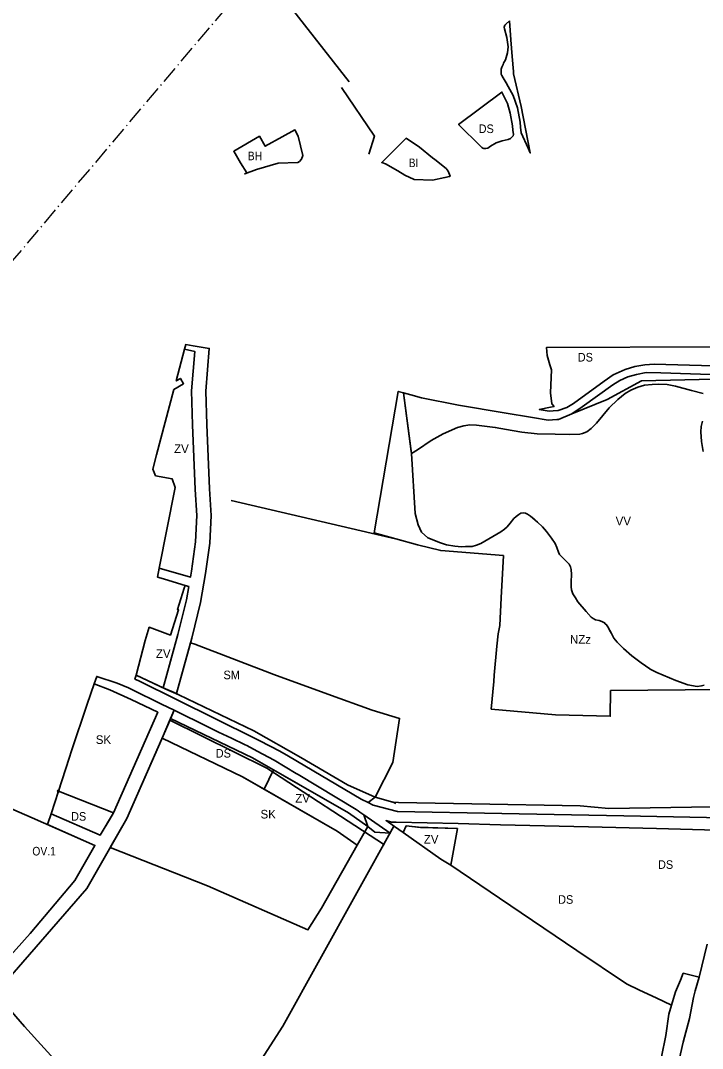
# Model space of a CAD drawing. Extents: x -650276 to -642489, y -1074311 to -1066658.
# Drawn here: x -646170 to -645218, y -1071706 to -1070271 of the extents above; entities that cross this region are included whole.
import ezdxf

# ---------------------------------------------------------------- set-up
doc = ezdxf.new("R2010")
doc.units = 0
doc.header["$LTSCALE"] = 4.8
doc.header["$PDMODE"] = 32
doc.header["$PDSIZE"] = 2.4
doc.linetypes.add('DOT_DASHED', pattern=[7.7, 5, -1.2, 0.3, -1.2])
for name, color, linetype, lineweight in [('1', 7, 'Continuous', 35), ('11', 7, 'Continuous', 35), ('15', 7, 'Continuous', 35), ('18', 7, 'Continuous', 35), ('2', 7, 'Continuous', 35), ('20', 7, 'Continuous', 35), ('24', 7, 'Continuous', 35), ('40', 7, 'Continuous', 35), ('45', 7, 'Continuous', 35), ('46', 7, 'Continuous', 35), ('54', 7, 'Continuous', 35), ('55', 7, 'Continuous', 53)]:
    doc.layers.add(name, color=color, linetype=linetype, lineweight=lineweight)
doc.layers.add('62', color=7, linetype='Continuous')

msp = doc.modelspace()

# ---------------------------------------------------------------- linework, layer by layer
at = {"layer": '1'}
msp.add_lwpolyline([(-645862.66, -1070469.5), (-645853.98, -1070483.81), (-645856.87, -1070485.24), (-645840.59, -1070479), (-645810.44, -1070470.17), (-645782.57, -1070469.22), (-645780.38, -1070467.64), (-645777.8, -1070464.4), (-645776.04, -1070459.38), (-645782.13, -1070432.59), (-645786.9, -1070423.81), (-645804.58, -1070433.53), (-645828.24, -1070446.54), (-645836.32, -1070432.55), (-645872.35, -1070453.55)], close=True, dxfattribs=at)
at = {"layer": '11'}
msp.add_lwpolyline([(-646066.165, -1071422.155), (-646153.5, -1071383.85), (-646208.577, -1071360.044), (-646241.68, -1071416.887), (-646258.487, -1071439.265), (-646275.615, -1071460.886), (-646289.976, -1071477.514), (-646330.914, -1071521.11), (-646324, -1071535), (-646217.978, -1071613.552), (-646211.407, -1071606.247), (-646156.471, -1071545.166), (-646094.063, -1071471.007)], close=True, dxfattribs=at)
at = {"layer": '15'}
for points in [[(-645487.361, -1070271.37), (-645491.94, -1070275.85), (-645491.94, -1070275.85), (-645493.8, -1070277.67), (-645494.57, -1070280.34), (-645494.12, -1070282.52), (-645490.79, -1070294.93), (-645489.31, -1070307.77), (-645490.03, -1070316.27), (-645493.05, -1070326.11), (-645495.44, -1070330.67), (-645496.12, -1070332.34), (-645497.83, -1070336.16), (-645498.75, -1070338.98), (-645499.01, -1070340.96), (-645499.09, -1070343.91), (-645498.74, -1070345.87), (-645498, -1070347.74), (-645496.02, -1070351.15), (-645491.97, -1070358.14), (-645488.99, -1070362.96)], [(-645487.361, -1070271.37), (-645491.94, -1070275.85), (-645491.94, -1070275.85), (-645493.8, -1070277.67), (-645494.57, -1070280.34), (-645494.12, -1070282.52), (-645490.79, -1070294.93), (-645489.31, -1070307.77), (-645490.03, -1070316.27), (-645493.05, -1070326.11), (-645495.44, -1070330.67), (-645496.12, -1070332.34), (-645497.83, -1070336.16), (-645498.75, -1070338.98), (-645499.01, -1070340.96), (-645499.09, -1070343.91), (-645498.74, -1070345.87), (-645498, -1070347.74), (-645496.02, -1070351.15), (-645491.97, -1070358.14)], [(-645458.32, -1070455.91), (-645471, -1070391), (-645481.67, -1070345.39), (-645481.65, -1070342.07), (-645483.34, -1070321.17), (-645484.27, -1070309.7), (-645485.21, -1070298.03), (-645487.361, -1070271.37)], [(-645483.34, -1070321.17), (-645484.27, -1070309.7), (-645485.21, -1070298.03), (-645487.361, -1070271.37)], [(-645482.16, -1070375.96), (-645476.12, -1070393.13), (-645472.61, -1070413.13), (-645471.87, -1070419.96), (-645470.99, -1070428.07), (-645461.32, -1070449.31), (-645458.32, -1070455.91), (-645471, -1070391), (-645481.67, -1070345.39), (-645481.65, -1070342.07), (-645483.34, -1070321.17)], [(-645491.97, -1070358.14), (-645488.99, -1070362.96), (-645482.16, -1070375.96)], [(-645488.99, -1070362.96), (-645482.16, -1070375.96), (-645476.12, -1070393.13), (-645472.61, -1070413.13), (-645471.87, -1070419.96), (-645470.99, -1070428.07), (-645461.32, -1070449.31), (-645458.32, -1070455.91)], [(-646197.398, -1071620.579), (-646077.593, -1071482.499), (-646021.674, -1071384.575), (-645964.396, -1071254.314), (-645955.342, -1071233.725), (-645973.324, -1071224.925), (-645989.7, -1071216.91), (-645997.62, -1071213.03), (-646019.41, -1071202.36), (-646035.06, -1071195.87), (-646063.59, -1071186.33), (-646067.097, -1071196.699), (-646045.462, -1071204.917), (-646015.387, -1071218.854), (-645978.403, -1071236.481), (-646040.084, -1071376.813), (-646058.719, -1071407.796), (-646127.301, -1071378.036), (-646131.79, -1071391.83), (-646132.229, -1071393.179), (-646066.165, -1071422.155), (-646094.063, -1071471.007), (-646156.471, -1071545.166), (-646211.407, -1071606.247)], [(-645701.44, -1071372.25), (-645782.32, -1071323.5), (-645784.92, -1071321.93), (-645815.65, -1071303.41), (-645839.37, -1071290.6), (-645854.1, -1071282.93), (-645856.26, -1071281.91), (-645875.48, -1071272.81), (-645893.41, -1071264.04), (-645907.62, -1071257.08), (-645955.342, -1071233.725), (-645960.34, -1071245.09), (-645846, -1071300), (-645712, -1071377), (-645712, -1071377)], [(-645712, -1071377), (-645685.098, -1071395.824), (-645690.677, -1071379.721)]]:
    msp.add_lwpolyline(points, dxfattribs=at)
for points in [[(-645911.345, -1070788.463), (-645906.373, -1070728.716), (-645929.077, -1070725.068), (-645939.27, -1070723.43), (-645940.955, -1070729.799), (-645926.784, -1070732.812), (-645931.369, -1070787.913), (-645930.036, -1070835.367), (-645926.084, -1070925.481), (-645923.919, -1070961.855), (-645925.626, -1070998.754), (-645931.24, -1071039.686), (-645932.635, -1071047.688), (-645976.17, -1071035.39), (-645978.58, -1071047.68), (-645973.77, -1071049.17), (-645968.97, -1071050.66), (-645940.25, -1071059.59), (-645934.978, -1071061.119), (-645938.15, -1071079.311), (-645950.283, -1071128.057), (-645970.966, -1071202.169), (-645952.419, -1071210.117), (-645930.943, -1071133.161), (-645918.57, -1071083.449), (-645911.474, -1071042.764), (-645905.69, -1071000.578), (-645903.891, -1070961.723), (-645906.11, -1070924.449), (-645910.048, -1070834.649)], [(-645694.15, -1071357.83), (-645684.785, -1071362.539), (-645674.947, -1071355.071), (-645713.428, -1071337.765), (-645778.69, -1071299.362), (-645844.079, -1071262.487), (-645948.761, -1071211.885), (-645967, -1071204), (-646008.714, -1071184.746), (-646010.14, -1071190.08), (-646004.65, -1071192.55), (-645951.118, -1071219.11), (-645843.45, -1071272.53), (-645835.76, -1071276.35), (-645808.13, -1071290.78), (-645795.97, -1071297.93), (-645694.15, -1071357.83)]]:
    msp.add_lwpolyline(points, close=True, dxfattribs=at)
msp.add_arc((-645538.107, -1071148.434), 277.076, 233.87926, 236.5888, dxfattribs=at)
at = {"layer": '18'}
for points in [[(-645926.81, -1071141.595), (-645932.502, -1071139.426), (-645952.419, -1071210.117), (-645948.761, -1071211.885)], [(-645678.86, -1071233.58), (-645741.09, -1071211.36), (-645816.47, -1071183.63), (-645926.81, -1071141.595)], [(-645948.761, -1071211.885), (-645844.079, -1071262.487), (-645778.69, -1071299.362), (-645713.428, -1071337.765), (-645674.947, -1071355.071)], [(-645674.947, -1071355.071), (-645650.09, -1071306.433), (-645640.737, -1071244.963), (-645678.86, -1071233.58)]]:
    msp.add_lwpolyline(points, dxfattribs=at)
at = {"layer": '2'}
msp.add_lwpolyline([(-645594.769, -1070494.065), (-645577.47, -1070490.3), (-645571.13, -1070488.89), (-645569.97, -1070488.3), (-645572.86, -1070481.41), (-645575.7, -1070477.77), (-645591.49, -1070465.19), (-645594.62, -1070462.7), (-645612.77, -1070447.82), (-645631.63, -1070435.3), (-645636.42, -1070439.93), (-645648.9, -1070452.38), (-645665.6, -1070469.04), (-645660.29, -1070471.12), (-645643.4, -1070481.02), (-645633.35, -1070486.91), (-645620.22, -1070493)], close=True, dxfattribs=at)
at = {"layer": '20'}
for points in [[(-645990.48, -1071263.958), (-645978.403, -1071236.481), (-646015.387, -1071218.854), (-646045.462, -1071204.917), (-646067.097, -1071196.699), (-646076.713, -1071225.138)], [(-646076.713, -1071225.138), (-646098.66, -1071290.03), (-646102.011, -1071300.326), (-646117.031, -1071346.48)], [(-646117.031, -1071346.48), (-646040.084, -1071376.813), (-645990.48, -1071263.958)]]:
    msp.add_lwpolyline(points, dxfattribs=at)
msp.add_lwpolyline([(-645699.825, -1071422.134), (-645728.105, -1071402.346), (-645859.986, -1071326.563), (-645972.422, -1071272.568), (-646021.674, -1071384.575), (-646044.948, -1071425.333), (-645909.13, -1071478.56), (-645768.62, -1071540.17), (-645749.631, -1071509.908)], close=True, dxfattribs=at)
msp.add_point((-646117.031, -1071346.48), dxfattribs=at)
at = {"layer": '24'}
for points in [[(-645497.81, -1070370.93), (-645497.81, -1070370.93), (-645490.19, -1070386.97), (-645486.54, -1070400.38), (-645483.29, -1070417.99), (-645482.62, -1070423.93), (-645481.93, -1070430.04), (-645482.18, -1070432.13), (-645485.67, -1070435.7), (-645489.34, -1070437.05), (-645497.33, -1070438.82), (-645505.88, -1070441.74), (-645513.81, -1070446.24), (-645517.44, -1070449.23), (-645517.95, -1070449.45), (-645520.4, -1070449.87), (-645521.41, -1070449.84), (-645522.95, -1070449.61), (-645524.42, -1070449.16), (-645525.75, -1070448.41), (-645527.34, -1070447.1), (-645558.36, -1070416.1)], [(-645202.41, -1070726.571), (-645197.539, -1070753.128), (-645202.96, -1070752.89), (-645285.11, -1070750.69), (-645298.41, -1070751.48), (-645312.2, -1070753.77), (-645325.82, -1070757.94), (-645342.41, -1070765.76), (-645354.98, -1070774.28), (-645398.04, -1070805.44), (-645407.37, -1070810.95), (-645419.18, -1070815.44), (-645426.36, -1070815.78), (-645432.07, -1070816.05), (-645445.81, -1070814.06), (-645429.993, -1070810.647), (-645424.969, -1070809.563), (-645428.39, -1070806.09), (-645430, -1070790.68), (-645428.73, -1070758.67), (-645430.84, -1070751.43), (-645434.53, -1070738.77), (-645435.711, -1070727.497)], [(-645829.706, -1071343.963), (-645816.714, -1071316.828), (-645846, -1071300), (-645960.34, -1071245.09), (-645972.422, -1071272.568), (-645859.986, -1071326.563)], [(-646045.393, -1071385.64), (-646040.084, -1071376.813), (-646117.031, -1071346.48), (-646127.301, -1071378.036), (-646058.719, -1071407.796)], [(-645675.177, -1071403.922), (-645675.177, -1071403.922), (-645653.742, -1071405.36), (-645690.677, -1071379.721), (-645685.098, -1071395.824)]]:
    msp.add_lwpolyline(points, close=True, dxfattribs=at)
for points in [[(-645179.18, -1070765.86), (-645275.8, -1070762.66), (-645296.51, -1070762.52), (-645309.78, -1070764.88), (-645321.9, -1070768.47), (-645333.12, -1070773.33), (-645342.94, -1070779.31), (-645385.99, -1070810.35), (-645400.05, -1070819.84), (-645351, -1070800), (-645303, -1070774), (-645182, -1070771)], [(-645204.341, -1071368.19), (-645348.55, -1071370.559), (-645388.619, -1071366.991), (-645539.738, -1071364.092), (-645642.431, -1071362.259), (-645650.28, -1071362.07), (-645674.947, -1071355.071), (-645684.785, -1071362.539), (-645677.58, -1071366.16), (-645643.56, -1071374.75), (-645497.84, -1071377.53), (-645327.76, -1071380.76), (-645166.34, -1071384.07)], [(-645164.76, -1071401.79), (-645281.92, -1071398.82), (-645376.87, -1071396.41), (-645499.65, -1071393.3), (-645558.9, -1071391.8), (-645645.368, -1071389.96), (-645651.93, -1071389.82), (-645659.6, -1071387.71), (-645647.727, -1071396.036), (-645635.795, -1071404.403), (-645631.44, -1071394.9), (-645614.201, -1071396.844), (-645560.11, -1071398.7), (-645569.07, -1071449.88), (-645501.37, -1071495.68), (-645393.34, -1071568.75), (-645324.17, -1071615.53), (-645324.17, -1071615.53), (-645305.78, -1071624.13), (-645282.54, -1071634.997), (-645261.094, -1071645.025), (-645255.662, -1071626.67), (-645248.786, -1071610.383), (-645244.81, -1071600.61), (-645222.48, -1071606.08), (-645222.48, -1071606.08), (-645211.27, -1071560.01)], [(-645222.48, -1071606.08), (-645244.81, -1071600.61), (-645248.786, -1071610.383), (-645255.662, -1071626.67)], [(-645222.48, -1071606.08), (-645244.81, -1071600.61), (-645248.786, -1071610.383), (-645255.662, -1071626.67)], [(-645339.904, -1072462.677), (-645347.551, -1072443.527), (-645347.677, -1072391.355), (-645346.62, -1072330.914), (-645343.458, -1072278.998), (-645339.908, -1072235.158), (-645335.367, -1072185.207), (-645325.498, -1072102.789), (-645309.01, -1071998.147), (-645285.617, -1071875.733), (-645244.798, -1071696.585), (-645235.793, -1071663.703), (-645230.436, -1071634.261), (-645227.905, -1071625.277), (-645222.48, -1071606.08)], [(-645339.904, -1072462.677), (-645347.551, -1072443.527), (-645347.677, -1072391.355), (-645346.62, -1072330.914), (-645343.458, -1072278.998), (-645339.908, -1072235.158), (-645335.367, -1072185.207), (-645325.498, -1072102.789), (-645309.01, -1071998.147), (-645285.617, -1071875.733), (-645244.798, -1071696.585), (-645235.793, -1071663.703), (-645230.436, -1071634.261), (-645227.905, -1071625.277), (-645222.48, -1071606.08)], [(-645255.662, -1071626.67), (-645261.094, -1071645.025), (-645264.841, -1071657.687), (-645269.077, -1071687.396), (-645274.868, -1071717.176), (-645286.175, -1071761.228), (-645300.076, -1071820.179), (-645313.153, -1071883.081), (-645326.343, -1071952.807)], [(-645255.662, -1071626.67), (-645261.094, -1071645.025), (-645264.841, -1071657.687), (-645269.077, -1071687.396), (-645274.868, -1071717.176), (-645286.175, -1071761.228), (-645300.076, -1071820.179), (-645313.153, -1071883.081)]]:
    msp.add_lwpolyline(points, dxfattribs=at)
at = {"layer": '40'}
for points in [[(-645932.635, -1071047.688), (-645931.24, -1071039.686), (-645925.626, -1070998.754), (-645923.919, -1070961.855), (-645926.084, -1070925.481), (-645930.036, -1070835.367), (-645931.369, -1070787.913), (-645926.784, -1070732.812), (-645940.955, -1070729.799), (-645952.65, -1070773.98), (-645946.81, -1070770.47), (-645942.3, -1070777.96), (-645955.86, -1070786.21), (-645980.01, -1070877.28), (-645985.28, -1070897.13), (-645981.48, -1070906.35), (-645958.21, -1070910.84), (-645954.01, -1070922.8), (-645954.492, -1070925.251), (-645976.17, -1071035.39)], [(-645970.966, -1071202.169), (-645950.283, -1071128.057), (-645938.15, -1071079.311), (-645934.978, -1071061.119), (-645940.25, -1071059.59), (-645941.45, -1071063.3), (-645950.96, -1071092.8), (-645949.21, -1071093.62), (-645960.66, -1071128.71), (-645990.14, -1071117.76), (-645995.74, -1071136.22), (-646008.714, -1071184.746)], [(-645712, -1071377), (-645816.714, -1071316.828), (-645829.706, -1071343.963), (-645728.105, -1071402.346), (-645699.825, -1071422.134), (-645685.098, -1071395.824)], [(-645583.18, -1071441.3), (-645580.947, -1071442.658), (-645569.07, -1071449.88), (-645560.11, -1071398.7), (-645611.58, -1071397.14), (-645631.44, -1071394.9), (-645635.795, -1071404.403)]]:
    msp.add_lwpolyline(points, close=True, dxfattribs=at)
at = {"layer": '45'}
for points in [[(-645217.086, -1070791.58), (-645233.003, -1070787.399), (-645255.407, -1070781.443), (-645267.315, -1070779.162), (-645279.349, -1070778.402), (-645288.343, -1070778.909), (-645298.731, -1070780.176), (-645307.923, -1070782.557), (-645317.677, -1070786.866), (-645325.785, -1070791.428), (-645336.046, -1070799.793), (-645348.318, -1070811.675), (-645366.02, -1070832.94), (-645373.241, -1070840.417), (-645379.448, -1070845.106), (-645385.148, -1070847.387), (-645389.329, -1070848.148), (-645404.15, -1070848.781), (-645423.364, -1070848.402), (-645448.7, -1070847.895), (-645470.235, -1070845.487), (-645483.61, -1070843.208), (-645507.299, -1070838.899), (-645533.268, -1070835.731), (-645542.642, -1070835.35), (-645550.832, -1070836.602), (-645560.079, -1070839.137), (-645579.841, -1070848.008), (-645596.689, -1070857.387), (-645615.817, -1070870.187), (-645624.321, -1070875.224), (-645618.798, -1070958.861), (-645615, -1070975), (-645610, -1070985), (-645601.41, -1070992.83), (-645583.707, -1071000.16), (-645575.406, -1071002.782), (-645563.698, -1071004.618), (-645554.524, -1071005.405), (-645548.534, -1071005.316), (-645539.622, -1071004.966), (-645533.156, -1071003.131), (-645527.302, -1071001.033), (-645521.535, -1070997.886), (-645499.204, -1070984.54), (-645494.223, -1070980.781), (-645490.641, -1070977.722), (-645486.534, -1070972.652), (-645481.466, -1070966.271), (-645477.971, -1070963.036), (-645474.301, -1070960.414), (-645471.418, -1070958.578), (-645468.185, -1070957.966), (-645464.865, -1070958.491), (-645462.069, -1070959.89), (-645457.875, -1070962.949), (-645452.982, -1070967.057), (-645448.001, -1070971.341), (-645441.361, -1070977.635), (-645435.443, -1070984.082), (-645428.541, -1070993.348), (-645423.648, -1071000.865), (-645421.21, -1071006.61), (-645419.026, -1071013.254), (-645417.453, -1071016.051), (-645412.735, -1071020.771), (-645407.492, -1071025.841), (-645404.172, -1071029.687), (-645402.194, -1071033.492), (-645401.408, -1071037.251), (-645400.796, -1071044.157), (-645401.233, -1071054.647), (-645401.408, -1071061.465), (-645400.796, -1071065.748), (-645398.979, -1071070.938), (-645395.234, -1071076.602), (-645395.222, -1071076.62), (-645391.902, -1071082.302), (-645380.193, -1071095.851), (-645373.291, -1071103.543), (-645370.698, -1071105.6), (-645367.028, -1071107.348), (-645362.223, -1071108.484), (-645358.326, -1071109.586), (-645358.203, -1071109.621), (-645354.883, -1071111.631)], [(-645216.991, -1070872.38), (-645219.351, -1070858.481), (-645220.312, -1070845.02), (-645219.787, -1070837.502), (-645217.778, -1070830.159)], [(-645354.883, -1071111.631), (-645353.555, -1071112.92), (-645352, -1071114.429), (-645349.99, -1071117.401), (-645347.631, -1071121.771), (-645345.097, -1071126.754), (-645341.689, -1071132.873), (-645336.884, -1071138.467), (-645328.059, -1071147.471), (-645316.308, -1071157.576), (-645303.551, -1071167.541), (-645291.581, -1071175.845), (-645290.83, -1071176.217), (-645281.707, -1071180.74), (-645254.845, -1071191.919), (-645238.506, -1071198.212), (-645225.487, -1071200.398), (-645225.487, -1071200.398), (-645219.283, -1071199.786), (-645215.351, -1071198.562)]]:
    msp.add_lwpolyline(points, dxfattribs=at)
at = {"layer": '46'}
for points in [[(-645182, -1070771), (-645303, -1070774), (-645351, -1070800), (-645400.05, -1070819.84), (-645418.67, -1070827.72), (-645421.09, -1070827.89), (-645433.49, -1070828.76), (-645455.184, -1070825.042), (-645494.82, -1070818.45), (-645558.3, -1070808), (-645610.25, -1070797.55), (-645625, -1070793.5), (-645635.482, -1070790.628), (-645624.513, -1070872.314), (-645624.321, -1070875.224), (-645615.817, -1070870.187), (-645596.689, -1070857.387), (-645579.841, -1070848.008), (-645560.079, -1070839.137), (-645550.832, -1070836.602), (-645542.642, -1070835.35), (-645533.268, -1070835.731), (-645507.299, -1070838.899), (-645483.61, -1070843.208), (-645470.235, -1070845.487), (-645448.7, -1070847.895), (-645423.364, -1070848.402), (-645404.15, -1070848.781), (-645389.329, -1070848.148), (-645385.148, -1070847.387), (-645379.448, -1070845.106), (-645373.241, -1070840.417), (-645366.02, -1070832.94), (-645348.318, -1070811.675), (-645336.046, -1070799.793), (-645325.785, -1070791.428), (-645317.677, -1070786.866), (-645307.923, -1070782.557), (-645298.731, -1070780.176), (-645288.343, -1070778.909), (-645279.349, -1070778.402), (-645267.315, -1070779.162), (-645255.407, -1070781.443), (-645233.003, -1070787.399), (-645217.086, -1070791.58)], [(-645346.31, -1071206.07), (-645189.902, -1071204.885), (-645130.749, -1070959.561), (-645098.438, -1070825.558), (-645100.268, -1070771.946), (-645143, -1070770), (-645161, -1070770)], [(-645225.487, -1071200.398), (-645238.506, -1071198.212), (-645254.845, -1071191.919), (-645281.707, -1071180.74), (-645290.83, -1071176.217), (-645291.581, -1071175.845), (-645303.551, -1071167.541), (-645316.308, -1071157.576), (-645328.059, -1071147.471), (-645336.884, -1071138.467), (-645341.689, -1071132.873), (-645345.097, -1071126.754), (-645349.99, -1071117.401), (-645352, -1071114.429), (-645354.883, -1071111.631), (-645358.203, -1071109.621), (-645362.223, -1071108.484), (-645367.028, -1071107.348), (-645370.698, -1071105.6), (-645373.291, -1071103.543), (-645380.193, -1071095.851), (-645391.902, -1071082.302), (-645395.222, -1071076.62), (-645398.979, -1071070.938), (-645400.796, -1071065.748), (-645401.408, -1071061.465), (-645401.233, -1071054.647), (-645400.796, -1071044.157), (-645401.408, -1071037.251), (-645402.194, -1071033.492), (-645404.172, -1071029.687), (-645407.492, -1071025.841), (-645412.735, -1071020.771), (-645417.453, -1071016.051), (-645419.026, -1071013.254), (-645421.21, -1071006.61), (-645423.648, -1071000.865), (-645428.541, -1070993.348), (-645435.443, -1070984.082), (-645441.361, -1070977.635), (-645448.001, -1070971.341), (-645457.875, -1070962.949), (-645462.069, -1070959.89), (-645464.865, -1070958.491), (-645468.185, -1070957.966), (-645471.418, -1070958.578), (-645474.301, -1070960.414), (-645477.971, -1070963.036), (-645481.466, -1070966.271), (-645486.534, -1070972.652), (-645490.641, -1070977.722), (-645494.223, -1070980.781), (-645499.204, -1070984.54), (-645521.535, -1070997.886), (-645527.302, -1071001.033), (-645533.156, -1071003.131), (-645539.622, -1071004.966), (-645548.534, -1071005.316), (-645554.524, -1071005.405), (-645563.698, -1071004.618), (-645575.406, -1071002.782), (-645583.707, -1071000.16), (-645601.41, -1070992.83), (-645610, -1070985), (-645615, -1070975), (-645618.798, -1070958.861), (-645624.321, -1070875.224), (-645635.482, -1070790.628), (-645642.52, -1070788.7), (-645676.292, -1070985.89), (-645615.899, -1071002.753), (-645583.18, -1071010.7), (-645495.87, -1071017.81), (-645498.931, -1071076.631)], [(-645217.778, -1070830.159), (-645219.787, -1070837.502), (-645220.312, -1070845.02), (-645219.351, -1070858.481), (-645216.991, -1070872.38)], [(-645498.931, -1071076.631), (-645500.94, -1071115.24), (-645503.08, -1071126.98), (-645504.79, -1071144.18), (-645508.912, -1071184.7)], [(-645508.912, -1071184.7), (-645509.22, -1071193.44), (-645512.84, -1071231.9), (-645423.08, -1071239.85)], [(-645215.351, -1071198.562), (-645219.283, -1071199.786), (-645219.283, -1071199.786), (-645225.487, -1071200.398), (-645225.487, -1071200.398)], [(-645423.08, -1071239.85), (-645346.67, -1071242.07), (-645346.31, -1071206.07)]]:
    msp.add_lwpolyline(points, dxfattribs=at)
at = {"layer": '54'}
for p, q in [((-645875.986, -1070940.86), (-645638.682, -1070996.266)), ((-645650.559, -1071361.544), (-645646.066, -1071363.608))]:
    msp.add_line(p, q, dxfattribs=at)
for points in [[(-645903.547, -1070057.381), (-645879.191, -1070130.665), (-645848.973, -1070180.543), (-645834.684, -1070241.324), (-645795.429, -1070249.201), (-645711.259, -1070356.569)], [(-645721.753, -1070364.565), (-645675.805, -1070432.543), (-645683.821, -1070457.746)], [(-645961.323, -1071247.326), (-645825.908, -1071314.509), (-645661.944, -1071421.517)], [(-645648.577, -1071395.44), (-645803.784, -1071674.386), (-645877, -1071788), (-645965, -1071892)], [(-646336.784, -1071524.232), (-646218.737, -1071612.767), (-646164.374, -1071674.897), (-645904.456, -1071961.331), (-645718.199, -1072151.712), (-645526.944, -1072343.922), (-645538, -1072384), (-645459, -1072440), (-645389, -1072483), (-645335, -1072526), (-645287, -1072569), (-645227, -1072617), (-645139.573, -1072694.628), (-645084.365, -1072788.086)]]:
    msp.add_lwpolyline(points, dxfattribs=at)
at = {"layer": '55', "linetype": 'DOT_DASHED', "lineweight": 25}
msp.add_line((-646590, -1071090), (-645744.292, -1070089.84), dxfattribs=at)

# ---------------------------------------------------------------- texts
at = {"layer": '62'}
for s, width, p in [('DS', 0.95, (-645530.386, -1070428.148)), ('BH', 0.9, (-645852.646, -1070466.101)), ('BI', 0.85, (-645627.657, -1070475.713)), ('DS', 0.95, (-645392, -1070747)), ('SM', 0.95, (-645886.606, -1071190.345)), ('DS', 0.95, (-645897.407, -1071299.717)), ('DS', 0.95, (-646099.407, -1071387.717)), ('OV.1', 0.9, (-646153.486, -1071436.306)), ('DS', 0.95, (-645279.957, -1071454.984)), ('DS', 0.95, (-645419.407, -1071503.717))]:
    msp.add_text(s, height=12, dxfattribs=dict(at, width=width)).set_placement(p)
for s, p in [('ZV', (-645955.588, -1070874.768)), ('VV', (-645339.075, -1070975.614)), ('NZz', (-645402.866, -1071140.823)), ('ZV', (-645980.931, -1071160.591)), ('SK', (-646064.883, -1071280.659)), ('ZV', (-645786.398, -1071362.507)), ('SK', (-645834.883, -1071384.659)), ('ZV', (-645606.931, -1071419.591))]:
    msp.add_text(s, height=12, dxfattribs=at).set_placement(p)

doc.saveas('drawing.dxf')
